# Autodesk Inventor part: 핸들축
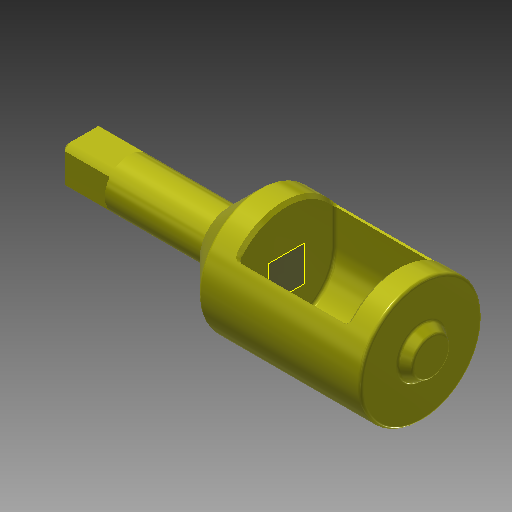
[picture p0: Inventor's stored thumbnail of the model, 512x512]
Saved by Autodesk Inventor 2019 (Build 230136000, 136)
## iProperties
Created: 2018-01
Part Number: 핸들축
Material: 강철, 연강
Document SubType Name: Modeling
Designer: mduedu
Density: 1 g/cm^3
Appearance: 노란색
Author: mduedu
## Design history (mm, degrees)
sketch "스케치1"
  geometry: L1 (0, 0)-(-109, 0); L2 (-46, -7.5)-(0, -7.5); L3 (0, -7.5)-(0, 0); L4 (-106, -19)-(-46, -19); L5 (-46, -19)-(-46, -7.5); L6 (-106, -7.5)-(-106, -19); L7 (-109, -5.768)-(-106, -7.5); L8 (-109, -5.768)-(-109, 0)
  constraints: 16 end point, 2 parallel, 1 horizontal, 1 vertical
  dimensions: "d8" = 15 diameter of L2 L1; "d43" = 46 distance between parallel lines of L3 L5; "d47" = 60 distance between parallel lines of L5 L6; "d63" = 3 distance between parallel lines of L6 L8; "d77" = 38 diameter of L4 L1; "d78" = 15 diameter of L6.start L1; "d79" = 30 deg angle of L1 L7
revolve "회전1" sketch "스케치1" stored, may be unused: angle "d9" = 90 deg
sketch "스케치4"
  geometry: L1 (-6, -6)-(-4.5, -6); L2 (6, -6)-(6, -4.5); L3 (6, 6)-(4.5, 6); L4 (-6, 6)-(-6, 4.5); L5 (-6, -6)-(6, 6); L6 (6, -6)-(-6, 6); L7 (-4.5, 6)-(-6, 6); L8 (-6, 4.5)-(-6, -4.5); L9 (-6, -4.5)-(-6, -6); L10 (-4.5, -6)-(4.5, -6); L11 (4.5, -6)-(6, -6); L12 (6, -4.5)-(6, 4.5); L13 (6, 4.5)-(6, 6); L14 (4.5, 6)-(-4.5, 6); C1 r 7.5 at (0, 0) reference; 2 further points
  constraints: 28 end point, 18 parallel, 9 perpendicular, 3 horizontal, 2 midpoint, 1 coincident, 11 other
  dimensions: "d20" = 12 distance of L4.start L3.start; "d21" = 12 distance of L3.start L2.start (= d20)
extrude "돌출2" cut sketch "스케치4" distance "d22" = 15; taper "d23" = 0 deg
chamfer "모따기2" distance "d24" = 1; stored, may be unused: second distance "d25" = 2, angle "d26" = 45 deg
sketch "스케치5"
  geometry: 2 further points
  constraints: 1 coincident
hole "구멍1" sketch "스케치5" at (5, 4.153) diameter "d27" = 2.459; stored, may be unused: countersink angle "d31" = 90 deg, drill point angle "d33" = 120 deg; dims "d28" = 6.9, "d29" = 4, "d30" = 2, "d32" = 8.4
node "작업 평면1"
sketch "스케치9"
  geometry: L1 (10, 4.153)-(10, 15.815); L2 (-20, 4.153)-(-20, 15.815); A1 r 15 centre (-5, 4.153) between (-20, 4.153) and (10, 4.153); A2 r 19 centre (-5, 4.153) between (10, 15.815) and (-20, 15.815) reference; 1 further point
  constraints: 4 end point, 4 point on circle, 2 tangent, 1 centre point, 1 coincident, 1 concentric, 1 parallel, 1 vertical
  dimensions: "d76" = 4 radial gap between concentric circles of A2 A1
extrude "돌출4" cut sketch "스케치9" distance "d73" = 34; taper "d74" = 0 deg
chamfer "모따기3" distance "d44" = 10; stored, may be unused: second distance "d45" = 2, angle "d46" = 45 deg
fillet "모깎기4" dims "d80" = 1
chamfer "모따기5" distance "d81" = 1; stored, may be unused: second distance "d82" = 2, angle "d83" = 45 deg
node "솔리드1"
other parameters: "d75" = -64
